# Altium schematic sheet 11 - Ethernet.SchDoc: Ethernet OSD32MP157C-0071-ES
size A3; Date: 01-DEC-2018; CompanyName: Octavo Systems LLC; Organization: Octavo Systems LLC; Address2: Austin, TX; Address3: USA; DocumentNumber: DK2 RefDes; Revision: C-01; SheetNumber: 11; SheetTotal: 14; Project: OSD32MP157C-0071
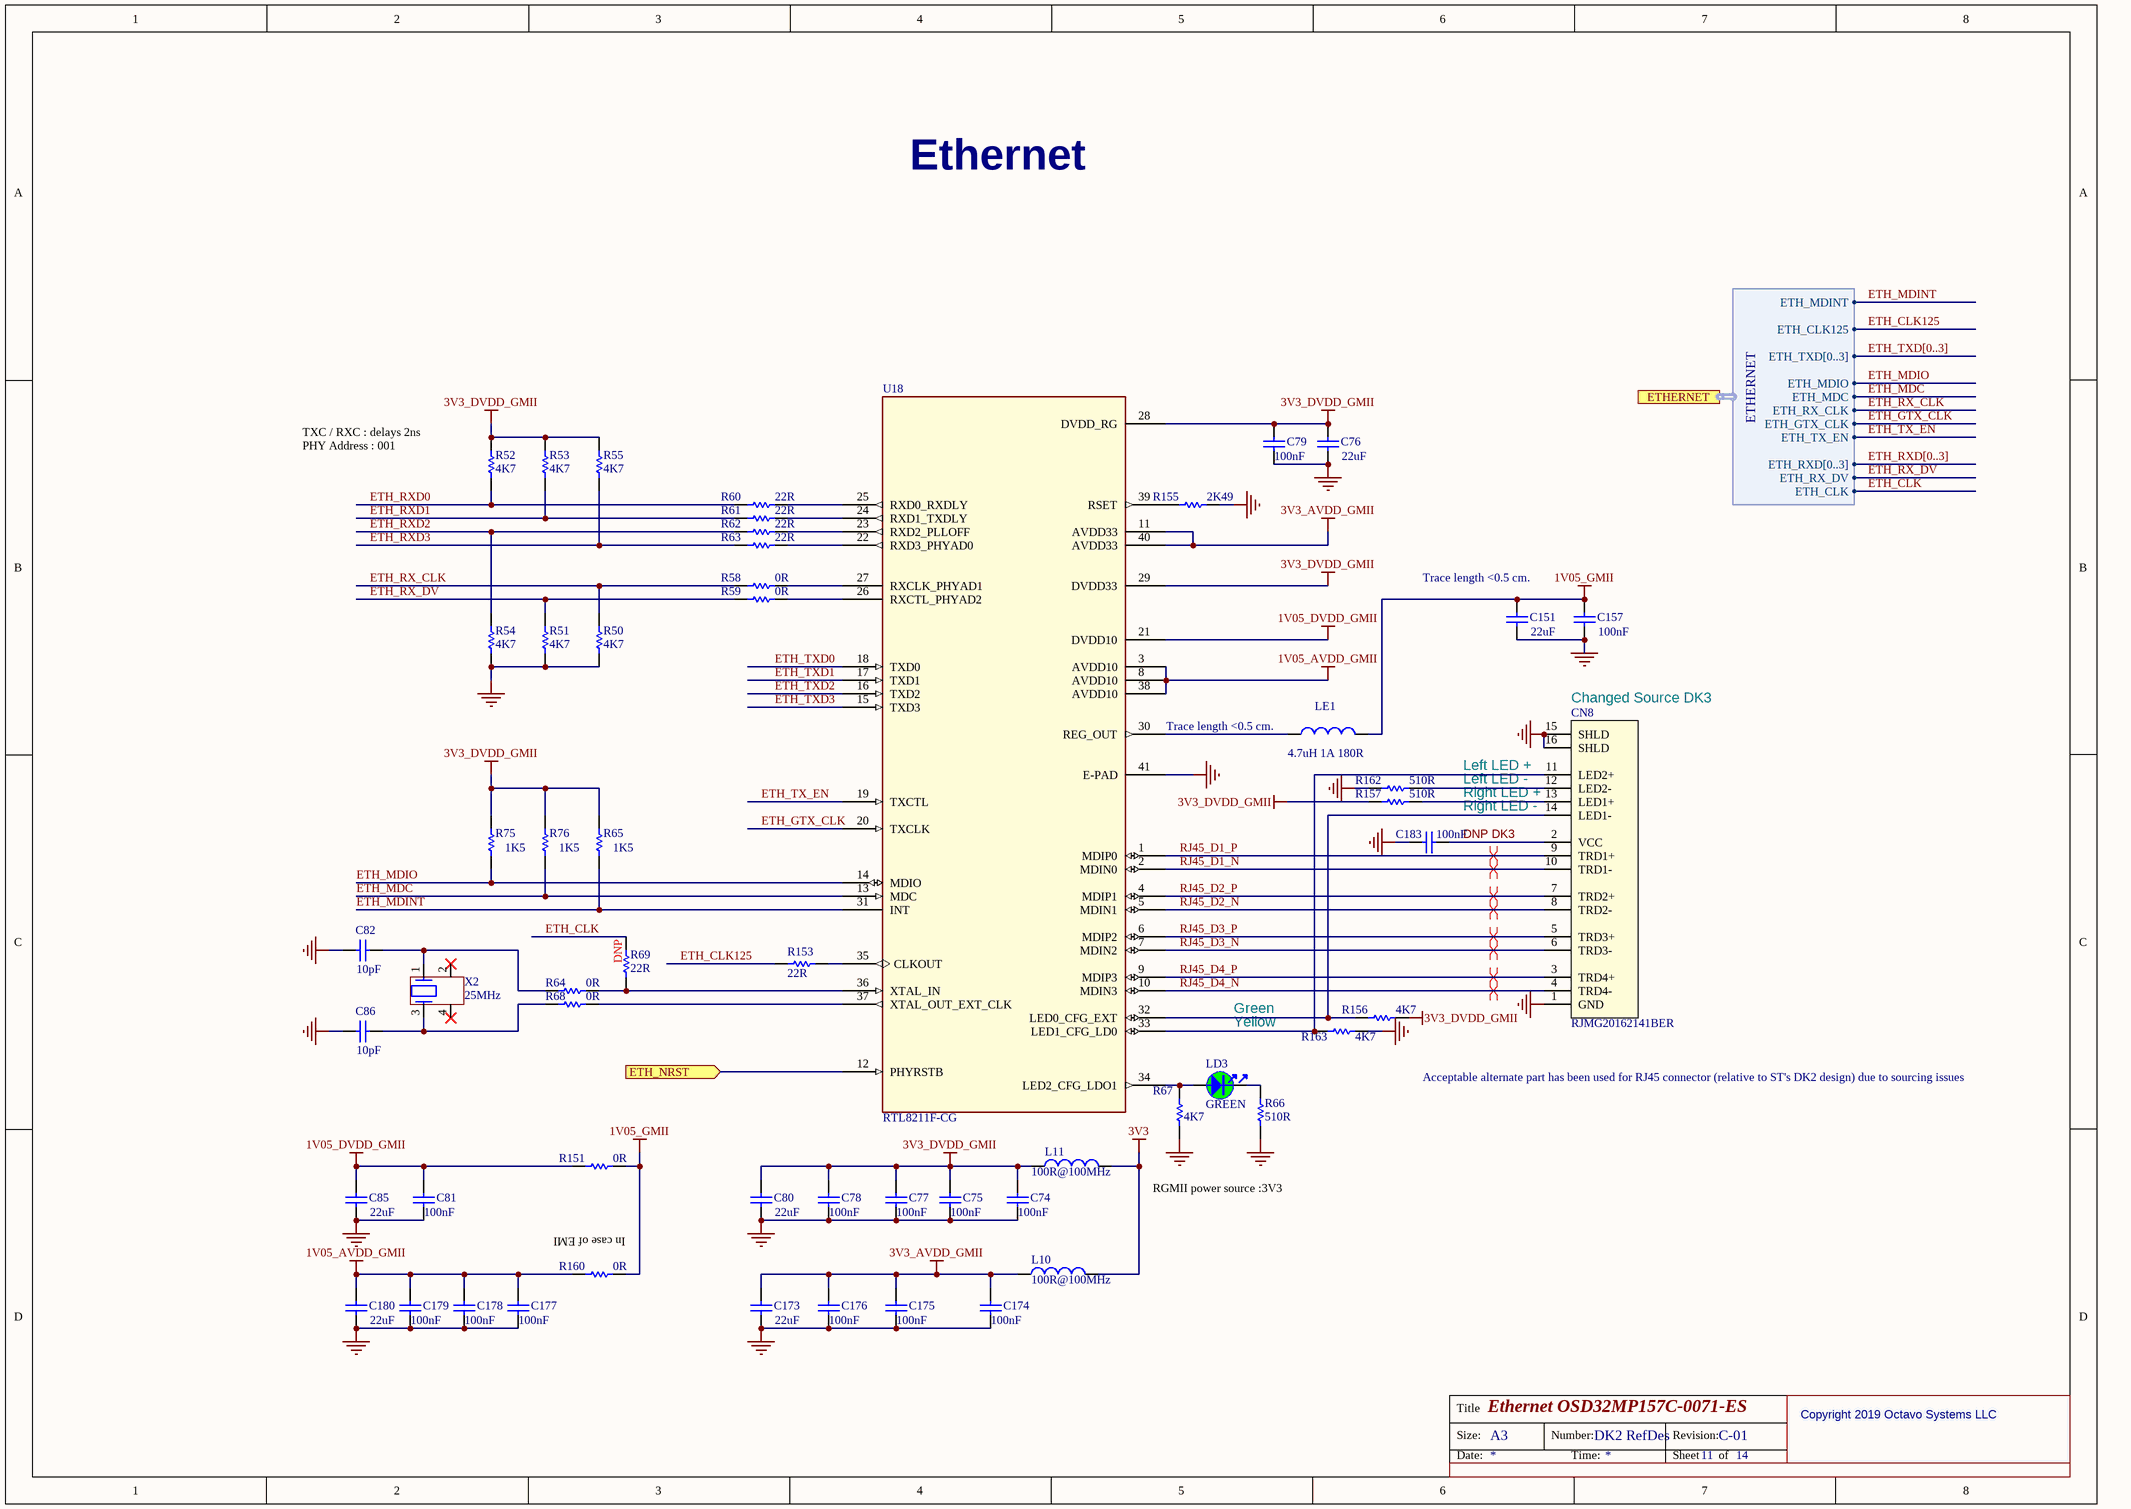
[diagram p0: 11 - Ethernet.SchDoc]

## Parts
C74  value 100nF  [C0402]
C75  value 100nF  [C0402]
C76  value 22uF  [C0603]
C77  value 100nF  [C0402]
C78  value 100nF  [C0402]
C79  value 100nF  [C0402]
C80  value 22uF  [C0603]
C81  value 100nF  [C0402]
C82  value 10pF  [C0402]
C85  value 22uF  [C0603]
C86  value 10pF  [C0402]
C151  value 22uF  [C0603]
C157  value 100nF  [C0402]
C173  value 22uF  [C0603]
C174  value 100nF  [C0402]
C175  value 100nF  [C0402]
C176  value 100nF  [C0402]
C177  value 100nF  [C0402]
C178  value 100nF  [C0402]
C179  value 100nF  [C0402]
C180  value 22uF  [C0603]
C183  value 100nF  [C0402]
CN8  RJMG20162141BER  [RJMG20162141BER]
L10  value 100R@100MHz  [FIL_0603_H0P65]
L11  value 100R@100MHz  [FIL_0603_H0P65]
LD3  value GREEN  [LED_0603_GREEN]
LE1  value 4.7uH 1A 180R  [L1210_LQH]
R50  value 4K7  [R0402]
R51  value 4K7  [R0402]
R52  value 4K7  [R0402]
R53  value 4K7  [R0402]
R54  value 4K7  [R0402]
R55  value 4K7  [R0402]
R58  value 0R  [R0402]
R59  value 0R  [R0402]
R60  value 22R  [R0402]
R61  value 22R  [R0402]
R62  value 22R  [R0402]
R63  value 22R  [R0402]
R64  value 0R  [R0402]
R65  value 1K5  [R0402]
R66  value 510R  [R0402]
R67  value 4K7  [R0402]
R68  value 0R  [R0402]
R69  value 22R  [R0402]  (no BOM)
R75  value 1K5  [R0402]
R76  value 1K5  [R0402]
R151  value 0R  [R0603]
R153  value 22R  [R0402]
R155  value 2K49  [R0402]
R156  value 4K7  [R0402]
R157  value 510R  [R0402]
R160  value 0R  [R0603]
R162  value 510R  [R0402]
R163  value 4K7  [R0402]
U18  RTL8211F-CG  [ICC_QFN40-EPAD_5X5_P040]
X2  value 25MHz  [CRY_NX3225HA_4P]  (hidden comment: XTAL_4_PINS)

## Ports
ETH_NRST (in), ETHERNET (harness ETHERNET)

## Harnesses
ETHERNET: ETH_MDINT, ETH_CLK125, ETH_TXD[0..3], ETH_MDIO, ETH_MDC, ETH_RX_CLK, ETH_GTX_CLK, ETH_TX_EN, ETH_RXD[0..3], ETH_RX_DV, ETH_CLK

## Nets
1V05_AVDD_GMII: C177.2 C178.2 C179.2 C180.2 R160.1 U18.3(AVDD10) U18.8(AVDD10) U18.38(AVDD10)
1V05_DVDD_GMII: C81.2 C85.2 R151.1 U18.21(DVDD10)
1V05_GMII: C151.2 C157.2 LE1.2 R151.2 R160.2
3V3: L10.2 L11.2
3V3_AVDD_GMII: C173.2 C174.2 C175.2 C176.2 L10.1 U18.11(AVDD33) U18.40(AVDD33)
3V3_DVDD_GMII: C74.2 C75.2 C76.1 C77.2 C78.2 C79.2 C80.2 L11.1 R52.2 R53.2 R55.2 R65.2 R75.2 R76.2 R156.1 R157.2 U18.28(DVDD_RG) U18.29(DVDD33)
GND: C74.1 C75.1 C76.2 C77.1 C78.1 C79.1 C80.1 C81.1 C82.1 C85.1 C86.1 C151.1 C157.1 C173.1 C174.1 C175.1 C176.1 C177.1 C178.1 C179.1 C180.1 C183.1 CN8.1(GND) CN8.15(SHLD) CN8.16(SHLD) R50.1 R51.1 R54.1 R66.1 R67.1 R155.2 R162.1 R163.1 U18.41(E-PAD)
ETH_CLK: R69.2 ; port ETHERNET.ETH_CLK
ETH_CLK125: R153.1 ; port ETHERNET.ETH_CLK125
ETH_GTX_CLK: U18.20(TXCLK) ; port ETHERNET.ETH_GTX_CLK
ETH_MDC: R76.1 U18.13(MDC) ; port ETHERNET.ETH_MDC
ETH_MDINT: R65.1 U18.31(INT) ; port ETHERNET.ETH_MDINT
ETH_MDIO: R75.1 U18.14(MDIO) ; port ETHERNET.ETH_MDIO
ETH_NRST: U18.12(PHYRSTB) ; port ETH_NRST
ETH_RX_CLK: R50.2 R58.1 ; port ETHERNET.ETH_RX_CLK
ETH_RX_DV: R51.2 R59.1 ; port ETHERNET.ETH_RX_DV
ETH_RXD0: R52.1 R60.1
ETH_RXD1: R53.1 R61.1
ETH_RXD2: R54.2 R62.1
ETH_RXD3: R55.1 R63.1
ETH_TX_EN: U18.19(TXCTL) ; port ETHERNET.ETH_TX_EN
ETH_TXD0: U18.18(TXD0)
ETH_TXD1: U18.17(TXD1)
ETH_TXD2: U18.16(TXD2)
ETH_TXD3: U18.15(TXD3)
RJ45_D1_N: CN8.10(TRD1-) U18.2(MDIN0)
RJ45_D1_P: CN8.9(TRD1+) U18.1(MDIP0)
RJ45_D2_N: CN8.8(TRD2-) U18.5(MDIN1)
RJ45_D2_P: CN8.7(TRD2+) U18.4(MDIP1)
RJ45_D3_N: CN8.6(TRD3-) U18.7(MDIN2)
RJ45_D3_P: CN8.5(TRD3+) U18.6(MDIP2)
RJ45_D4_N: CN8.4(TRD4-) U18.10(MDIN3)
RJ45_D4_P: CN8.3(TRD4+) U18.9(MDIP3)
NetC82_2: C82.2 R64.1 X2.1
NetC86_2: C86.2 R68.1 X2.3
NetC183_2: C183.2 CN8.2(VCC)
NetCN8_11: CN8.11(LED2+) R163.2 U18.33(LED1_CFG_LD0)
NetCN8_12: CN8.12(LED2-) R162.2
NetCN8_13: CN8.13(LED1+) R157.1
NetCN8_14: CN8.14(LED1-) R156.2 U18.32(LED0_CFG_EXT)
NetLD3_1: LD3.1 R67.2 U18.34(LED2_CFG_LDO1)
NetLD3_2: LD3.2 R66.2
NetLE1_1: LE1.1 U18.30(REG_OUT)
NetR58_2: R58.2 U18.27(RXCLK_PHYAD1)
NetR59_2: R59.2 U18.26(RXCTL_PHYAD2)
NetR60_2: R60.2 U18.25(RXD0_RXDLY)
NetR61_2: R61.2 U18.24(RXD1_TXDLY)
NetR62_2: R62.2 U18.23(RXD2_PLLOFF)
NetR63_2: R63.2 U18.22(RXD3_PHYAD0)
NetR64_2: R64.2 R69.1 U18.36(XTAL_IN)
NetR68_2: R68.2 U18.37(XTAL_OUT_EXT_CLK)
NetR153_2: R153.2 U18.35(CLKOUT)
NetR155_1: R155.1 U18.39(RSET)

Not connected (* = marked no-connect by the designer): X2 2* 4*

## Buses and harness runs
bus ETH_RXD[0..3]
bus ETH_TXD[0..3]

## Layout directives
differential pair: RJ45_D1_N, RJ45_D1_P, RJ45_D2_N, RJ45_D2_P, RJ45_D3_N, RJ45_D3_P, RJ45_D4_N, RJ45_D4_P

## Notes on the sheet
- Ethernet
- (near R52) TXC / RXC : delays 2ns
  PHY Address : 001
- Trace length <0.5 cm.
- (near CN8) Changed Source DK3
- (near LE1) Trace length <0.5 cm.
- Left LED +
- Left LED -
- (near C183) DNP DK3
- (near CN8) Right LED +
- Right LED -
- (near R69) DNP
- Yellow
- Green
- Acceptable alternate part has been used for RJ45 connector (relative to ST's DK2 design) due to sourcing issues
- (near R160) In case of EMI
- RGMII power source :3V3
- 506 West 14th Street, Suite C Austin, TX 78701
- Proprietary and Confidential
- Copyright 2015-2018 Octavo Systems LLC
- Copyright 2019 Octavo Systems LLC

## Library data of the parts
C74 C75 C77-C79 C81 C157 C174-C179 C183 = MCD-00006: Capacitor,100nF,16V,X7R,10%,0402; Manufacturer_Part_Number: CC0402KRX7R7BB104; Manufacturer: YAGEO; Provided_By: Subcon; Initial_Board_Reference: mb1274
C76 C80 C85 C151 C173 C180 = MCD-00100: Capacitor,22uF,6V3,X5R,20%,0603; Manufacturer_Part_Number: GRM188R60J226MEA0J; Manufacturer: MURATA; ECCN_US: EAR99; ECCN_EU: NEC; Provided_By: Subcon; Initial_Board_Reference: mb1262
C82 C86 = MCD-00015: Capacitor,10pF,50V,NPO,5%,0402; Manufacturer_Part_Number: CC0402JRNPO9BN100; Manufacturer: YAGEO; Provided_By: subcon; Initial_Board_Reference: mb1274
CN8 = RJMG20162141BER: CONN MAGJACK 1PORT 1000 BASE-T
L10 L11 = MCD-00094: Ferrite bead 100R 2A 0603; Manufacturer_Part_Number: BLM18EG101TN1; Manufacturer: MURATA; Part_Type: Inductor; ECCN_US: EAR99; ECCN_EU: NEC; Provided_By: Subcon; Initial_Board_Reference: mb1262
LD3 = MCD-00050: LED, Green, 0603; Manufacturer_Part_Number: 19-213SYGC/S530-E2/TR8; Manufacturer: EVERLIGHT; Part_Type: Display; ECCN_US: EAR99; ECCN_EU: NEC; Provided_By: Subcon; Initial_Board_Reference: mb1274
LE1 = MCD-00048: FIXED IND 4.7UH 1A 180 MOHM 30% SMD; Manufacturer_Part_Number: LQH32PN4R7NN0L; Manufacturer: MURATA; Provided_By: Subcon; Initial_Board_Reference: mb1274
R50-R55 R67 R156 R163 = MCD-00065: Resistor,4K7,0402,1%,1/16W; Manufacturer_Part_Number: RC0402FR-074K7L; Manufacturer: YAGEO; Alternate_Manufacturer_Part_Number: RT0402FRE074K7L; Provided_By: Subcon; Initial_Board_Reference: mb1274
R58 R59 R64 R68 = MCD-00052: Resistor,0R,0402,5%,1/16W; Manufacturer_Part_Number: RC0402JR-070RL; Manufacturer: YAGEO; Provided_By: Subcon; Initial_Board_Reference: mb1274
R60-R63 R69 R153 = MCD-00189: Resistor,22R,0402,1%,1/16W; Manufacturer_Part_Number: RC0402FR-0722RL; Manufacturer: YAGEO; Provided_By: Subcon
R65 R75 R76 = MCD-00068: Resistor,1K5,0402,1%,1/16W; Manufacturer_Part_Number: RC0402FR-071K5L; Manufacturer: YAGEO; Provided_By: Subcon; Initial_Board_Reference: mb1274
R66 R157 R162 = MCD-00064: Resistor,510R,0402,1%,1/16W; Manufacturer_Part_Number: RC0402FR-07510RL; Manufacturer: YAGEO; Provided_By: Subcon; Initial_Board_Reference: mb1274
R151 R160 = MCD-00056: Resistor,0R,0603,5%,1/10W; Manufacturer_Part_Number: RC0603JR-070RL; Manufacturer: YAGEO; Provided_By: subcon; Initial_Board_Reference: mb1274
R155 = MCD-00183: Resistor,2K49,0402,1%,1/16W; Manufacturer_Part_Number: RC0402FR-072K49L; Manufacturer: YAGEO; Provided_By: Subcon
U18 = MCD-01130: 10/100/1000M GIGABIT Ethernet Transceiver, QFN40 , SMPS version; Manufacturer: REALTEK; Part_Type: IC; Provided_By: Subcon; Initial_Board_Reference: MB1272
X2 = MCD-01463: Crystal 25Mhz, 10pF, -+50PPM, SMD; Part_Type: Crystal_Osc; Manufacturer_Part_Number: NX3225GA 25MHz EXS00A-CG06750; Manufacturer: NDK; Provided_By: SUBCO; Initial_Board_Reference: MB1272B; Remark: footprint same as CRY_NX3225HA_4P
